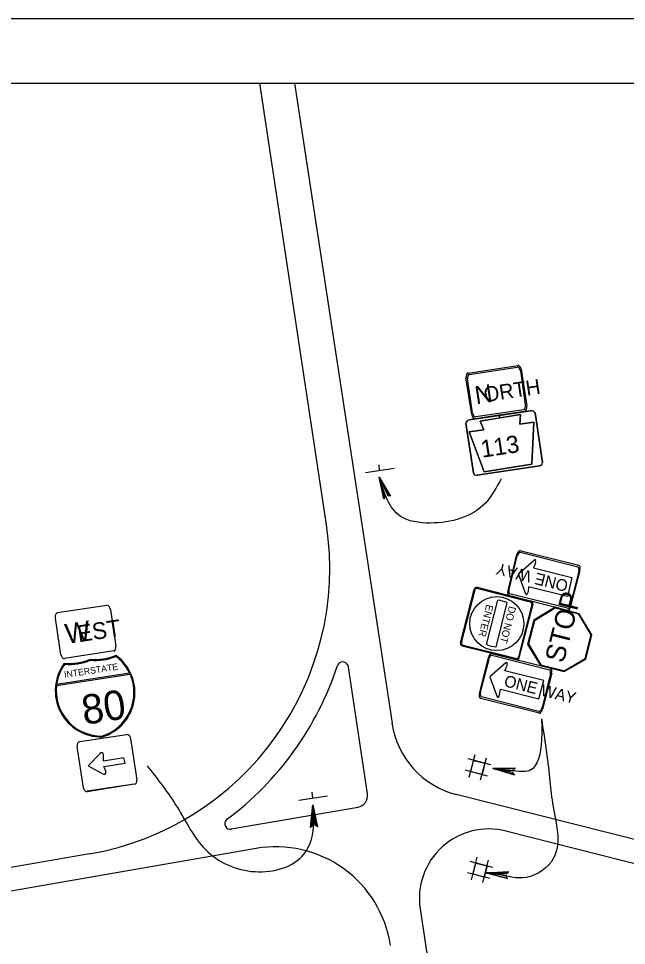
# Model space of a CAD drawing. Extents: x 640994 to 644422, y 298458 to 299646.
# Drawn here: x 642997.9 to 643138.7, y 299430.9 to 299645.6 of the extents above; entities that cross this region are included whole.
import ezdxf

# ---------------------------------------------------------------- set-up
doc = ezdxf.new("R2010")
doc.units = 0
for name, color, linetype in [('1', 7, 'Continuous'), ('2', 7, 'Continuous'), ('XCS-GRID-MIN', 7, 'Continuous')]:
    doc.layers.add(name, color=color, linetype=linetype)

msp = doc.modelspace()

# ---------------------------------------------------------------- linework, layer by layer
at = {"layer": '1'}
msp.add_line((642716.31, 299630.63), (643502.31, 299630.63), dxfattribs=at)
at = {"layer": '2'}
for p, q in [((643053.69, 299630.63), (643069.19, 299528.38)), ((643061.81, 299630.63), (643084.44, 299482.38)), ((643102.06, 299563.5), (643113.56, 299565.25)), ((643102.31, 299563.13), (643113.44, 299564.88)), ((643102.94, 299553.88), (643101.56, 299562.38)), ((643114.19, 299564), (643115.31, 299556.13)), ((643114.31, 299564.38), (643115.69, 299555.88)), ((643103.06, 299554.25), (643101.94, 299562.13)), ((643108.69, 299559.13), (643108.69, 299559.13)), ((643102.31, 299552.63), (643116.56, 299554.75)), ((643116.56, 299554.75), (643102.31, 299552.63)), ((643115.19, 299554.63), (643103.69, 299552.88)), ((643114.94, 299555), (643103.81, 299553.38)), ((643114.19, 299553.88), (643109.56, 299553.13)), ((643114.06, 299551.63), (643114.19, 299553.88)), ((643117.56, 299554.25), (643119.31, 299542.75)), ((643119.31, 299542.75), (643117.56, 299554.25)), ((643103.31, 299540.38), (643101.56, 299551.88)), ((643101.56, 299551.88), (643103.31, 299540.38)), ((643102.31, 299552.63), (643102.31, 299552.63)), ((643109.56, 299553.13), (643104.81, 299552.38)), ((643104.81, 299552.38), (643105.69, 299550.38)), ((643117.31, 299552.13), (643114.06, 299551.63)), ((643116.81, 299542.38), (643117.31, 299552.13)), ((643105.69, 299550.38), (643102.31, 299549.88)), ((643102.31, 299549.88), (643105.81, 299540.63)), ((643110.44, 299547.25), (643110.44, 299547.25)), ((643110.44, 299547.25), (643110.44, 299547.25)), ((643084.94, 299541.38), (643078.31, 299540.38)), ((643081.56, 299540.88), (643081.44, 299542.25)), ((643118.56, 299542), (643104.19, 299539.88)), ((643104.19, 299539.88), (643118.56, 299542)), ((643105.81, 299540.63), (643116.81, 299542.38)), ((643114.06, 299522.38), (643127.69, 299519)), ((643114.19, 299522), (643127.44, 299518.63)), ((643111.31, 299513.13), (643113.31, 299521.5)), ((643111.56, 299513.38), (643113.44, 299521.13)), ((643113.69, 299517), (643117.44, 299520.25)), ((643117.69, 299519.5), (643117.19, 299518.38)), ((643117.19, 299518.38), (643126.06, 299516.13)), ((643127.69, 299517.5), (643125.69, 299509.75)), ((643127.94, 299517.75), (643125.81, 299509.5)), ((643115.44, 299512.25), (643113.69, 299517)), ((643119.56, 299515.5), (643119.56, 299515.5)), ((643126.06, 299516.13), (643125.06, 299511.75)), ((643100.31, 299501), (643103.44, 299513.38)), ((643100.56, 299501), (643103.69, 299513.25)), ((643104.19, 299513.88), (643116.69, 299510.63)), ((643104.31, 299513.63), (643116.44, 299510.5)), ((643116.06, 299514), (643115.94, 299512.88)), ((643125.06, 299511.75), (643116.06, 299514)), ((643106.31, 299500.63), (643108.94, 299510.88)), ((643125.06, 299508.5), (643111.44, 299512)), ((643125.06, 299509), (643111.69, 299512.38)), ((643006.94, 299508), (643018.31, 299509.75)), ((643019.19, 299508.75), (643020.44, 299500.25)), ((643111.06, 299510.38), (643108.44, 299500)), ((643116.81, 299509.88), (643113.69, 299497.75)), ((643117.06, 299510), (643113.81, 299497.5)), ((643007.69, 299498.25), (643006.44, 299506.75)), ((643108.69, 299505.5), (643108.69, 299505.5)), ((643013.44, 299503.5), (643013.44, 299503.5)), ((643113.19, 299497.13), (643100.69, 299500.25)), ((643113.06, 299497.38), (643100.94, 299500.38)), ((643123.31, 299501.75), (643123.31, 299501.75)), ((643019.94, 299499.13), (643008.56, 299497.38)), ((643107.56, 299498.5), (643121.19, 299495.13)), ((643107.56, 299498.13), (643120.94, 299494.75)), ((643008.56, 299496), (643008.56, 299496)), ((643014.56, 299497), (643014.56, 299497)), ((643020.44, 299497.88), (643020.44, 299497.88)), ((643074.19, 299495.88), (643078.69, 299466)), ((643104.69, 299489.25), (643106.81, 299497.63)), ((643104.94, 299489.63), (643106.94, 299497.25)), ((643110.81, 299496.38), (643107.06, 299493.13)), ((643023.56, 299494), (643006.69, 299491.38)), ((643006.69, 299491.13), (643023.69, 299493.75)), ((643110.56, 299494.5), (643111.06, 299495.63)), ((643119.56, 299492.25), (643110.56, 299494.5)), ((643121.06, 299493.63), (643119.19, 299486)), ((643121.44, 299494), (643119.31, 299485.63)), ((643107.06, 299493.13), (643108.81, 299488.5)), ((643113.06, 299491.63), (643113.06, 299491.63)), ((643113.06, 299491.63), (643113.06, 299491.63)), ((643118.44, 299488), (643119.56, 299492.25)), ((643109.31, 299489), (643109.56, 299490.25)), ((643109.56, 299490.25), (643118.44, 299488)), ((643015.81, 299488.25), (643015.81, 299488.25)), ((643118.56, 299484.75), (643104.94, 299488.13)), ((643118.44, 299485.13), (643105.19, 299488.5)), ((643012.06, 299478.13), (643022.94, 299479.75)), ((643012.06, 299478.13), (643022.94, 299479.75)), ((643012.06, 299478.13), (643022.94, 299479.75)), ((643023.81, 299478.88), (643025.31, 299469.25)), ((643023.81, 299478.88), (643025.31, 299469.25)), ((643023.81, 299478.88), (643025.31, 299469.25)), ((643012.94, 299467.38), (643011.44, 299477)), ((643012.94, 299467.38), (643011.44, 299477)), ((643012.94, 299467.38), (643011.44, 299477)), ((643016.81, 299475.38), (643014.06, 299472.5)), ((643017.56, 299473.63), (643017.56, 299475.13)), ((643022.31, 299474.38), (643017.56, 299473.63)), ((643022.56, 299473.13), (643022.31, 299474.38)), ((643102.31, 299469.88), (643103.69, 299475.13)), ((643104.94, 299469.25), (643106.31, 299474.38)), ((643014.06, 299472.5), (643017.44, 299470.63)), ((643017.69, 299472.38), (643022.56, 299473.13)), ((643018.19, 299471.13), (643017.69, 299472.38)), ((643018.44, 299473.13), (643018.44, 299473.13)), ((643107.31, 299472.75), (643102.06, 299474.13)), ((643106.56, 299470.13), (643101.44, 299471.5)), ((643024.69, 299468.25), (643013.81, 299466.63)), ((643024.69, 299468.25), (643013.81, 299466.63)), ((643024.69, 299468.25), (643013.81, 299466.5)), ((643066.06, 299465), (643065.94, 299466.38)), ((643244.81, 299429), (643099.31, 299465.88)), ((643069.44, 299465.5), (643062.81, 299464.5)), ((643076.56, 299462.88), (643047.19, 299457.88)), ((643284.81, 299413.38), (643110.81, 299457.38)), ((643052.94, 299453.38), (642815.06, 299412)), ((643014.31, 299452.13), (642808.19, 299416.25)), ((643102.81, 299446.13), (643104.19, 299451.38)), ((643107.81, 299449), (643102.56, 299450.38)), ((643105.44, 299445.5), (643106.81, 299450.63)), ((643107.06, 299446.38), (643101.94, 299447.75)), ((643090.94, 299439.38), (643101.94, 299367))]:
    msp.add_line(p, q, dxfattribs=at)
for points in [[(643102.31, 299552.63), (643101.86, 299552.4), (643101.6, 299552.17), (643101.56, 299551.88), (643103.31, 299540.38), (643103.52, 299539.91), (643103.95, 299539.83), (643104.19, 299539.88), (643118.56, 299542), (643119.03, 299542.24), (643119.24, 299542.51), (643119.31, 299542.75), (643117.56, 299554.25), (643117.31, 299554.56), (643116.82, 299554.82), (643116.56, 299554.75), (643109.26, 299553.72), (643109.37, 299553.1), (643114.19, 299553.88), (643114.06, 299551.63), (643117.31, 299552.13), (643116.81, 299542.38), (643105.81, 299540.63), (643102.31, 299549.88), (643105.69, 299550.38), (643104.81, 299552.38), (643109.37, 299553.1), (643109.25, 299553.71)], [(643103.31, 299473.75), (643105.94, 299473.13), (643105.31, 299470.5), (643102.69, 299471.13)], [(643103.81, 299450), (643106.44, 299449.38), (643105.81, 299446.75), (643103.19, 299447.38)]]:
    msp.add_lwpolyline(points, close=True, dxfattribs=at)
for points in [[(643082.69, 299534.63), (643082.94, 299535), (643081.44, 299539.38), (643082.69, 299534.63), (643082.56, 299534.38), (643081.44, 299539.38), (643083.44, 299535.13), (643083.81, 299535.13), (643081.44, 299539.38), (643084.06, 299535), (643083.81, 299535.13)], [(643124.31, 299494.38), (643129.31, 299497.25), (643130.69, 299502.88), (643127.81, 299507.75), (643122.19, 299509.25), (643117.31, 299506.25), (643115.81, 299500.63), (643118.81, 299495.75), (643124.31, 299494.38)], [(643124.31, 299494.5), (643129.19, 299497.38), (643130.56, 299502.88), (643127.69, 299507.63), (643122.19, 299509), (643117.44, 299506.13), (643116.06, 299500.75), (643118.94, 299495.88), (643124.44, 299494.5)], [(643112.56, 299470.63), (643112.44, 299471), (643107.81, 299471.88), (643112.56, 299470.63), (643112.81, 299470.38), (643107.81, 299471.88), (643112.56, 299471.5), (643112.69, 299471.88), (643107.81, 299471.88), (643113.06, 299472), (643112.69, 299471.88)], [(643065.81, 299458.5), (643066.06, 299458.75), (643066.06, 299463.5), (643065.81, 299458.5), (643065.56, 299458.25), (643066.06, 299463.5), (643066.56, 299458.75), (643066.94, 299458.63), (643066.06, 299463.5), (643067.19, 299458.38), (643066.94, 299458.63)], [(643111.06, 299446.5), (643110.94, 299447), (643106.19, 299447.75), (643111.06, 299446.5), (643111.19, 299446.38), (643106.19, 299447.75), (643110.94, 299447.5), (643111.19, 299447.75), (643106.19, 299447.75), (643111.44, 299448), (643111.19, 299447.75)]]:
    msp.add_lwpolyline(points, dxfattribs=at)
msp.add_circle((643108.7, 299505.46), 6.26, dxfattribs=at)
for centre, radius, start, end in [((643002.81, 299518.3), 67.19, 279.8697, 8.6538), ((643104.02, 299513.28), 0.559, 75.7794, 165.7794), ((643104.14, 299513.08), 0.517, 75.7794, 165.7794), ((643108.69, 299505.41), 5.45, 64.3582, 87.2006), ((643116.29, 299510), 0.517, 345.7794, 75.7794), ((643116.49, 299510.12), 0.559, 345.7794, 75.7794), ((643100.87, 299500.82), 0.559, 165.7794, 255.7794), ((643101.07, 299500.94), 0.517, 165.7794, 255.7794), ((643108.72, 299505.51), 5.45, 244.3582, 267.2006), ((643015.69, 299509.47), 12.33, 264.4038, 292.9038), ((643014.13, 299489.46), 10.73, 286.7839, 53.6538), ((643017.13, 299489.92), 10.73, 143.6538, 270.5237), ((643017.13, 299489.92), 10.51, 144.3462, 171.8611), ((643009.69, 299508.55), 12.33, 264.4038, 292.9038), ((643009.69, 299508.55), 12.56, 264.9943, 292.6428), ((643015.69, 299509.47), 12.56, 264.6648, 292.3133), ((643014.13, 299489.46), 10.51, 25.4466, 52.9614), ((643002.81, 299518.3), 72.56, 306.6068, 341.9288), ((643073, 299495.29), 1.31, 24.3383, 157.5626), ((643113.21, 299497.86), 0.517, 255.7794, 345.7794), ((643113.33, 299497.66), 0.559, 255.7794, 345.7794), ((643014.13, 299489.46), 10.51, 286.7839, 24.1669), ((643017.13, 299489.92), 10.51, 173.1407, 270.5237), ((643104.32, 299485.4), 20.16, 188.6538, 255.7794), ((643017.1, 299475.09), 0.46, 356.9014, 140.8081), ((643017.71, 299470.97), 0.46, 238.5129, 19.1785), ((643076.07, 299465.58), 2.69, 279.8696, 8.6536), ((643046.97, 299459.1), 1.3, 133.1831, 281.0673), ((643106.88, 299441.78), 16.13, 75.7793, 188.6538), ((643057.5, 299426.88), 26.88, 8.6538, 99.8697)]:
    msp.add_arc(centre, radius, start, end, dxfattribs=at)
for centre, major_axis, ratio, start_param, end_param in [((643113.58, 299563.89), (-0.15, 0.983), 0.6, 4.712389, 6.283185), ((643113.72, 299564.23), (-0.16, 1.06), 0.6, 4.712389, 6.283185), ((643102.25, 299562.48), (0.16, -1.06), 0.6, 3.141593, 4.712389), ((643102.48, 299562.2), (0.15, -0.983), 0.6, 3.141593, 4.712389), ((643114.78, 299556.02), (-0.15, 0.983), 0.6, 3.141593, 4.712389), ((643103.54, 299553.98), (0.16, -1.06), 0.6, 4.712389, 6.283185), ((643103.68, 299554.33), (0.15, -0.983), 0.6, 4.712389, 6.283185), ((643115.02, 299555.73), (-0.16, 1.06), 0.6, 3.141593, 4.712389), ((643116.71, 299554.12), (-0.797, -0.121), 0.8, 3.141593, 4.712389), ((643116.71, 299554.12), (-0.797, -0.121), 0.8, 3.141593, 4.712389), ((643102.36, 299551.94), (-0.797, -0.121), 0.8, 4.712389, 6.283185), ((643102.36, 299551.94), (-0.797, -0.121), 0.8, 4.712389, 6.283185), ((643118.46, 299542.64), (0.797, 0.121), 0.8, 4.712389, 6.283185), ((643118.46, 299542.64), (0.797, 0.121), 0.8, 4.712389, 6.283185), ((643104.11, 299540.46), (0.797, 0.121), 0.8, 3.141593, 4.712389), ((643104.11, 299540.46), (0.797, 0.121), 0.8, 3.141593, 4.712389), ((643113.86, 299521.35), (-0.26, -1.04), 0.4667, 3.141593, 4.712389), ((643113.92, 299521.01), (-0.244, -0.964), 0.4667, 3.141593, 4.712389), ((643117.43, 299519.73), (0.142, 0.56), 0.4667, 4.423888, 6.899163), ((643127.25, 299517.63), (0.244, 0.964), 0.4667, 4.712389, 6.283185), ((643127.48, 299517.9), (0.26, 1.04), 0.4667, 4.712389, 6.283185), ((643111.75, 299513.02), (-0.26, -1.04), 0.4667, 4.712389, 6.283185), ((643111.97, 299513.29), (-0.244, -0.964), 0.4667, 4.712389, 6.283185), ((643115.66, 299512.73), (0.142, 0.56), 0.4667, 2.525615, 5.00089), ((643018.53, 299508.64), (-0.16, 1.06), 0.6, 4.712389, 6.283185), ((643125.3, 299509.91), (0.244, 0.964), 0.4667, 3.141593, 4.712389), ((643125.36, 299509.56), (0.26, 1.04), 0.4667, 3.141593, 4.712389), ((643007.05, 299506.9), (0.16, -1.06), 0.6, 3.141593, 4.712389), ((643019.82, 299500.14), (-0.16, 1.06), 0.6, 3.141593, 4.712389), ((643008.35, 299498.39), (0.16, -1.06), 0.6, 4.712389, 6.283185), ((643107.27, 299497.52), (-0.26, -1.04), 0.4667, 3.141593, 4.712389), ((643107.34, 299497.17), (-0.244, -0.964), 0.4667, 3.141593, 4.712389), ((643110.85, 299495.91), (0.142, 0.56), 0.4667, 4.423888, 6.899163), ((643120.67, 299493.8), (0.244, 0.964), 0.4667, 4.712389, 6.283185), ((643120.89, 299494.07), (0.26, 1.04), 0.4667, 4.712389, 6.283185), ((643105.38, 299489.45), (-0.244, -0.964), 0.4667, 4.712389, 6.283185), ((643105.16, 299489.18), (-0.26, -1.04), 0.4667, 4.712389, 6.283185), ((643109.07, 299488.91), (0.142, 0.56), 0.4667, 2.525615, 5.00089), ((643118.71, 299486.08), (0.244, 0.964), 0.4667, 3.141593, 4.712389), ((643118.78, 299485.73), (0.26, 1.04), 0.4667, 3.141593, 4.712389), ((643023.14, 299478.83), (-0.14, 0.921), 0.769266, 4.712389, 6.283185), ((643023.14, 299478.83), (-0.14, 0.921), 0.769266, 4.712389, 6.283185), ((643023.14, 299478.83), (-0.14, 0.921), 0.769266, 4.712389, 6.283185), ((643012.15, 299477.16), (0.14, -0.921), 0.769266, 3.141593, 4.712389), ((643012.15, 299477.16), (0.14, -0.921), 0.769266, 3.141593, 4.712389), ((643012.15, 299477.16), (0.14, -0.921), 0.769266, 3.141593, 4.712389), ((643024.61, 299469.16), (-0.14, 0.921), 0.769266, 3.141593, 4.712389), ((643024.61, 299469.16), (-0.14, 0.921), 0.769266, 3.141593, 4.712389), ((643024.61, 299469.16), (-0.14, 0.921), 0.769266, 3.141593, 4.712389), ((643013.62, 299467.49), (0.14, -0.921), 0.769266, 4.712389, 6.283185), ((643013.62, 299467.49), (0.14, -0.921), 0.769266, 4.712389, 6.283185), ((643013.62, 299467.49), (0.14, -0.921), 0.769266, 4.712389, 6.283185)]:
    msp.add_ellipse(centre, major_axis=major_axis, ratio=ratio, start_param=start_param, end_param=end_param, dxfattribs=at)
for points in [[(643109.69, 299539), (643106.06, 299533.38), (643093.31, 299528.75), (643086.31, 299530.38), (643081.44, 299539.38)], [(643119.06, 299483.38), (643120.94, 299469.67), (643121.61, 299463.86), (643121.79, 299451.02), (643115.55, 299446.66), (643108.81, 299447.5)], [(643119.06, 299483.38), (643119.06, 299478.38), (643116.22, 299471.37), (643112.31, 299471.38), (643110.17, 299471.43)], [(643027.69, 299472.5), (643034.69, 299462.88), (643041.19, 299453.13), (643052.69, 299448), (643064.06, 299452.13), (643066.31, 299459.38), (643066.06, 299463.5)]]:
    msp.add_spline(points, degree=3, dxfattribs=at)
at = {"layer": 'XCS-GRID-MIN'}
msp.add_lwpolyline([(642676.31, 299645.63), (643517.31, 299645.63), (643517.31, 299051.63), (642676.31, 299051.63)], close=True, dxfattribs=at)

# ---------------------------------------------------------------- texts
at = {"layer": '2'}
for s, height, rotation, p in [('N', 4.16, 8.6525, (643103.94, 299556.25)), ('ORTH', 3.487, 8.6538, (643105.94, 299556.75)), ('113', 4, 8.6536, (643105.31, 299543.88)), ('ONE WAY', 2.687, 165.779, (643125.44, 299515.38)), ('STOP', 4.541, 75.7795, (643124.19, 299496.13)), ('ENTER', 1.677, 255.781, (643106.31, 299510)), ('DO NOT', 1.677, 255.7793, (643111.56, 299509.63)), ('W', 4.63, 8.6525, (643009.06, 299500.75)), ('EST', 3.875, 8.6538, (643011.81, 299501.13)), ('INTERSTATE', 1.517, 8.6538, (643008.56, 299492.88)), ('ONE WAY', 2.687, 345.779, (643110.19, 299491)), ('80', 6.829, 8.6538, (643013.06, 299482))]:
    msp.add_text(s, height=height, rotation=rotation, dxfattribs=at).set_placement(p)

doc.saveas('drawing.dxf')
